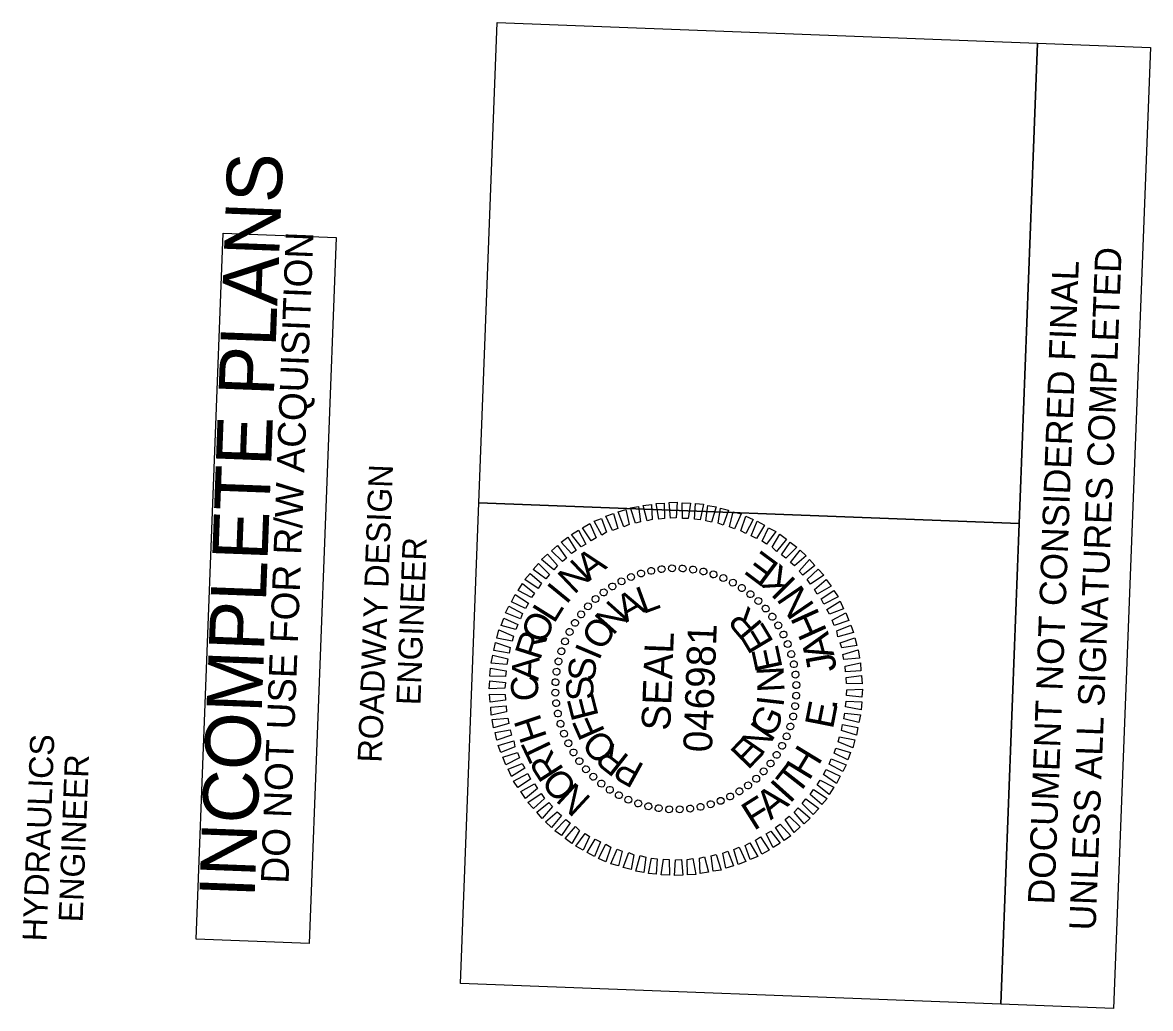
# Model space of a CAD drawing. Extents: x 2097431 to 2097897, y 685861 to 686794.
# Drawn here: x 2097476.5 to 2097570.4, y 686712.1 to 686794.1 of the extents above; entities that cross this region are included whole.
import ezdxf

# ---------------------------------------------------------------- set-up
doc = ezdxf.new("R2010")
doc.units = 0
for name, color, linetype in [('Sheet PE Seal Cell', 7, 'Continuous'), ('Sheet Profile CELL', 7, 'Continuous'), ('Sheet Sticker Exception Certification CELL', 7, 'Continuous'), ('Sheet Sticker Incomplete CELL', 7, 'Continuous')]:
    doc.layers.add(name, color=color, linetype=linetype)

msp = doc.modelspace()

# ---------------------------------------------------------------- linework, layer by layer
at = {"layer": 'Sheet PE Seal Cell'}
for p, q in [((2097527.187, 686748.023), (2097527.187, 686748.023)), ((2097527.998, 686748.312), (2097527.998, 686748.312)), ((2097528.847, 686748.52), (2097528.847, 686748.52)), ((2097529.732, 686748.646), (2097529.732, 686748.646)), ((2097530.596, 686748.733), (2097530.596, 686748.733)), ((2097531.476, 686748.719), (2097531.476, 686748.719)), ((2097532.353, 686748.625), (2097532.353, 686748.625)), ((2097533.207, 686748.453), (2097533.207, 686748.453)), ((2097534.04, 686748.241), (2097534.04, 686748.241)), ((2097534.869, 686747.929), (2097534.869, 686747.929)), ((2097525.615, 686747.223), (2097525.615, 686747.223)), ((2097526.392, 686747.653), (2097526.392, 686747.653)), ((2097535.654, 686747.538), (2097535.654, 686747.538)), ((2097536.418, 686747.109), (2097536.418, 686747.109)), ((2097524.214, 686746.176), (2097524.214, 686746.176)), ((2097524.896, 686746.75), (2097524.896, 686746.75)), ((2097537.119, 686746.581), (2097537.119, 686746.581)), ((2097537.797, 686746.015), (2097537.797, 686746.015)), ((2097523.59, 686745.579), (2097523.59, 686745.579)), ((2097538.394, 686745.392), (2097538.394, 686745.392)), ((2097522.497, 686744.2), (2097522.497, 686744.2)), ((2097523.024, 686744.9), (2097523.024, 686744.9)), ((2097538.968, 686744.709), (2097538.968, 686744.709)), ((2097522.067, 686743.436), (2097522.067, 686743.436)), ((2097539.441, 686743.99), (2097539.441, 686743.99)), ((2097539.872, 686743.213), (2097539.872, 686743.213)), ((2097521.677, 686742.65), (2097521.677, 686742.65)), ((2097540.241, 686742.419), (2097540.241, 686742.419)), ((2097521.365, 686741.822), (2097521.365, 686741.822)), ((2097540.53, 686741.607), (2097540.53, 686741.607)), ((2097521.153, 686740.989), (2097521.153, 686740.989)), ((2097540.738, 686740.758), (2097540.738, 686740.758)), ((2097520.98, 686740.135), (2097520.98, 686740.135)), ((2097540.864, 686739.873), (2097540.864, 686739.873)), ((2097520.886, 686739.258), (2097520.886, 686739.258)), ((2097530.912, 686738.693), (2097530.912, 686738.693)), ((2097540.951, 686739.009), (2097540.951, 686739.009)), ((2097520.872, 686738.378), (2097520.872, 686738.378)), ((2097540.937, 686738.129), (2097540.937, 686738.129)), ((2097520.959, 686737.514), (2097520.959, 686737.514)), ((2097521.085, 686736.628), (2097521.085, 686736.628)), ((2097540.844, 686737.252), (2097540.844, 686737.252)), ((2097521.293, 686735.78), (2097521.293, 686735.78)), ((2097540.671, 686736.398), (2097540.671, 686736.398)), ((2097521.582, 686734.968), (2097521.582, 686734.968)), ((2097540.459, 686735.565), (2097540.459, 686735.565)), ((2097521.952, 686734.173), (2097521.952, 686734.173)), ((2097539.756, 686733.951), (2097539.756, 686733.951)), ((2097540.147, 686734.737), (2097540.147, 686734.737)), ((2097522.382, 686733.396), (2097522.382, 686733.396)), ((2097539.327, 686733.187), (2097539.327, 686733.187)), ((2097522.855, 686732.678), (2097522.855, 686732.678)), ((2097523.43, 686731.995), (2097523.43, 686731.995)), ((2097538.8, 686732.487), (2097538.8, 686732.487)), ((2097524.026, 686731.372), (2097524.026, 686731.372)), ((2097537.61, 686731.211), (2097537.61, 686731.211)), ((2097538.233, 686731.808), (2097538.233, 686731.808)), ((2097524.705, 686730.805), (2097524.705, 686730.805)), ((2097525.405, 686730.278), (2097525.405, 686730.278)), ((2097536.209, 686730.164), (2097536.209, 686730.164)), ((2097536.927, 686730.637), (2097536.927, 686730.637)), ((2097526.169, 686729.849), (2097526.169, 686729.849)), ((2097526.955, 686729.458), (2097526.955, 686729.458)), ((2097527.784, 686729.146), (2097527.784, 686729.146)), ((2097534.637, 686729.364), (2097534.637, 686729.364)), ((2097535.432, 686729.734), (2097535.432, 686729.734)), ((2097528.616, 686728.934), (2097528.616, 686728.934)), ((2097529.47, 686728.761), (2097529.47, 686728.761)), ((2097530.347, 686728.668), (2097530.347, 686728.668)), ((2097531.227, 686728.654), (2097531.227, 686728.654)), ((2097532.091, 686728.741), (2097532.091, 686728.741)), ((2097532.977, 686728.867), (2097532.977, 686728.867)), ((2097533.825, 686729.075), (2097533.825, 686729.075))]:
    msp.add_line(p, q, dxfattribs=at)
for points in [[(2097526.586, 686752.189), (2097526.113, 686753.428), (2097526.741, 686753.624), (2097527.013, 686752.373)], [(2097527.557, 686752.472), (2097527.147, 686753.769), (2097527.811, 686753.863), (2097527.982, 686752.596)], [(2097528.526, 686752.675), (2097528.194, 686753.949), (2097528.878, 686754.043), (2097528.95, 686752.779)], [(2097529.492, 686752.818), (2097529.262, 686754.128), (2097529.944, 686754.162), (2097529.975, 686752.88)], [(2097530.456, 686752.901), (2097530.346, 686754.206), (2097531.027, 686754.22), (2097530.937, 686752.923)], [(2097531.456, 686752.883), (2097531.446, 686754.184), (2097532.125, 686754.158), (2097531.936, 686752.865)], [(2097532.454, 686752.825), (2097532.544, 686754.122), (2097533.202, 686754.057), (2097532.933, 686752.766)], [(2097533.41, 686752.688), (2097533.579, 686753.962), (2097534.255, 686753.856), (2097533.886, 686752.57)], [(2097534.423, 686752.489), (2097534.63, 686753.722), (2097535.305, 686753.556), (2097534.837, 686752.313)], [(2097524.758, 686751.499), (2097524.101, 686752.645), (2097524.731, 686752.881), (2097525.147, 686751.724)], [(2097525.633, 686751.865), (2097525.078, 686753.068), (2097525.728, 686753.303), (2097526.08, 686752.048)], [(2097535.372, 686752.192), (2097535.68, 686753.421), (2097536.334, 686753.256), (2097535.786, 686752.016)], [(2097536.32, 686751.856), (2097536.727, 686753.081), (2097537.337, 686752.798), (2097536.731, 686751.62)], [(2097537.184, 686751.422), (2097537.691, 686752.644), (2097538.299, 686752.32), (2097537.616, 686751.206)], [(2097523.019, 686750.525), (2097522.217, 686751.536), (2097522.812, 686751.894), (2097523.408, 686750.75)], [(2097523.859, 686751.013), (2097523.14, 686752.101), (2097523.754, 686752.458), (2097524.269, 686751.277)], [(2097538.088, 686750.987), (2097538.631, 686752.107), (2097539.239, 686751.784), (2097538.459, 686750.733)], [(2097522.217, 686749.955), (2097521.353, 686750.909), (2097521.909, 686751.308), (2097522.627, 686750.219)], [(2097538.929, 686750.475), (2097539.572, 686751.571), (2097540.116, 686751.15), (2097539.277, 686750.141)], [(2097539.706, 686749.845), (2097540.426, 686750.898), (2097540.991, 686750.496), (2097540.075, 686749.57)], [(2097520.744, 686748.59), (2097519.736, 686749.45), (2097520.234, 686749.911), (2097521.058, 686748.959)], [(2097521.471, 686749.283), (2097520.564, 686750.178), (2097521.062, 686750.64), (2097521.802, 686749.571)], [(2097540.442, 686749.216), (2097541.261, 686750.225), (2097541.764, 686749.766), (2097540.791, 686748.922)], [(2097520.095, 686747.855), (2097519.024, 686748.636), (2097519.484, 686749.139), (2097520.389, 686748.224)], [(2097541.175, 686748.487), (2097542.033, 686749.475), (2097542.474, 686748.958), (2097541.482, 686748.155)], [(2097519.464, 686747.058), (2097518.332, 686747.802), (2097518.771, 686748.306), (2097519.721, 686747.489)], [(2097541.849, 686747.801), (2097542.762, 686748.647), (2097543.223, 686748.149), (2097542.114, 686747.41)], [(2097518.894, 686746.3), (2097517.776, 686746.883), (2097518.139, 686747.469), (2097519.149, 686746.67)], [(2097542.438, 686746.978), (2097543.43, 686747.8), (2097543.829, 686747.245), (2097542.683, 686746.588)], [(2097518.399, 686745.398), (2097517.239, 686745.943), (2097517.543, 686746.551), (2097518.636, 686745.829)], [(2097543.008, 686746.195), (2097544.056, 686746.896), (2097544.415, 686746.362), (2097543.231, 686745.746)], [(2097517.985, 686744.513), (2097516.744, 686745.021), (2097517.005, 686745.571), (2097518.143, 686744.967)], [(2097543.474, 686745.297), (2097544.582, 686745.995), (2097544.878, 686745.363), (2097543.699, 686744.908)], [(2097517.591, 686743.628), (2097516.363, 686743.975), (2097516.587, 686744.587), (2097517.747, 686744.042)], [(2097543.921, 686744.419), (2097545.064, 686745.016), (2097545.32, 686744.385), (2097544.084, 686743.972)], [(2097517.294, 686742.678), (2097516.003, 686742.928), (2097516.189, 686743.601), (2097517.41, 686743.094)], [(2097544.307, 686743.524), (2097545.486, 686743.999), (2097545.703, 686743.39), (2097544.407, 686743.019)], [(2097517.035, 686741.667), (2097515.763, 686741.896), (2097515.889, 686742.552), (2097517.114, 686742.145)], [(2097544.589, 686742.532), (2097545.806, 686742.946), (2097545.962, 686742.319), (2097544.713, 686742.107)], [(2097516.839, 686740.714), (2097515.543, 686740.844), (2097515.688, 686741.499), (2097516.937, 686741.191)], [(2097544.812, 686741.563), (2097546.087, 686741.934), (2097546.201, 686741.249), (2097544.896, 686741.139)], [(2097516.741, 686739.717), (2097515.441, 686739.767), (2097515.487, 686740.426), (2097516.779, 686740.196)], [(2097544.995, 686740.595), (2097546.286, 686740.866), (2097546.321, 686740.204), (2097545.036, 686740.113)], [(2097545.078, 686739.631), (2097546.366, 686739.802), (2097546.419, 686739.119), (2097545.12, 686739.149)], [(2097516.684, 686738.759), (2097515.381, 686738.709), (2097515.426, 686739.367), (2097516.722, 686739.238)], [(2097545.14, 686738.628), (2097546.443, 686738.678), (2097546.397, 686738.019), (2097545.101, 686738.149)], [(2097516.745, 686737.756), (2097515.458, 686737.585), (2097515.404, 686738.267), (2097516.704, 686738.238)], [(2097545.083, 686737.67), (2097546.382, 686737.62), (2097546.337, 686736.961), (2097545.044, 686737.191)], [(2097516.828, 686736.792), (2097515.537, 686736.521), (2097515.502, 686737.183), (2097516.787, 686737.274)], [(2097544.985, 686736.673), (2097546.281, 686736.543), (2097546.135, 686735.888), (2097544.886, 686736.196)], [(2097517.012, 686735.824), (2097515.736, 686735.453), (2097515.623, 686736.137), (2097516.928, 686736.248)], [(2097544.788, 686735.719), (2097546.06, 686735.491), (2097545.935, 686734.835), (2097544.71, 686735.242)], [(2097517.235, 686734.855), (2097516.018, 686734.441), (2097515.862, 686735.067), (2097517.111, 686735.28)], [(2097517.517, 686733.863), (2097516.338, 686733.388), (2097516.121, 686733.997), (2097517.416, 686734.367)], [(2097544.529, 686734.709), (2097545.82, 686734.459), (2097545.634, 686733.786), (2097544.413, 686734.293)], [(2097517.903, 686732.968), (2097516.759, 686732.371), (2097516.503, 686733.001), (2097517.74, 686733.414)], [(2097543.838, 686732.874), (2097545.08, 686732.366), (2097544.818, 686731.815), (2097543.681, 686732.419)], [(2097544.232, 686733.759), (2097545.46, 686733.412), (2097545.236, 686732.8), (2097544.076, 686733.345)], [(2097518.349, 686732.09), (2097517.242, 686731.392), (2097516.946, 686732.024), (2097518.124, 686732.479)], [(2097543.424, 686731.989), (2097544.584, 686731.444), (2097544.28, 686730.835), (2097543.187, 686731.558)], [(2097518.815, 686731.191), (2097517.768, 686730.491), (2097517.408, 686731.025), (2097518.592, 686731.64)], [(2097542.929, 686731.087), (2097544.048, 686730.504), (2097543.685, 686729.917), (2097542.675, 686730.717)], [(2097519.386, 686730.409), (2097518.393, 686729.586), (2097517.994, 686730.142), (2097519.141, 686730.799)], [(2097542.36, 686730.329), (2097543.492, 686729.585), (2097543.052, 686729.081), (2097542.103, 686729.898)], [(2097519.975, 686729.586), (2097519.062, 686728.74), (2097518.6, 686729.238), (2097519.709, 686729.976)], [(2097520.649, 686728.9), (2097519.79, 686727.912), (2097519.35, 686728.429), (2097520.341, 686729.232)], [(2097541.729, 686729.532), (2097542.799, 686728.751), (2097542.34, 686728.248), (2097541.434, 686729.163)], [(2097521.381, 686728.171), (2097520.562, 686727.162), (2097520.059, 686727.621), (2097521.032, 686728.464)], [(2097541.08, 686728.796), (2097542.088, 686727.937), (2097541.59, 686727.476), (2097540.766, 686728.428)], [(2097522.118, 686727.542), (2097521.397, 686726.489), (2097520.832, 686726.891), (2097521.748, 686727.817)], [(2097522.894, 686726.912), (2097522.252, 686725.816), (2097521.708, 686726.237), (2097522.547, 686727.246)], [(2097539.607, 686727.432), (2097540.471, 686726.478), (2097539.915, 686726.079), (2097539.196, 686727.167)], [(2097540.353, 686728.104), (2097541.259, 686727.208), (2097540.761, 686726.747), (2097540.022, 686727.816)], [(2097523.735, 686726.399), (2097523.192, 686725.279), (2097522.584, 686725.603), (2097523.365, 686726.654)], [(2097537.965, 686726.374), (2097538.684, 686725.286), (2097538.069, 686724.929), (2097537.554, 686726.11)], [(2097538.804, 686726.862), (2097539.606, 686725.851), (2097539.012, 686725.493), (2097538.415, 686726.637)], [(2097524.639, 686725.964), (2097524.132, 686724.743), (2097523.524, 686725.067), (2097524.207, 686726.181)], [(2097525.503, 686725.531), (2097525.096, 686724.306), (2097524.486, 686724.589), (2097525.092, 686725.767)], [(2097526.451, 686725.194), (2097526.144, 686723.965), (2097525.49, 686724.13), (2097526.038, 686725.37)], [(2097536.191, 686725.521), (2097536.745, 686724.319), (2097536.096, 686724.084), (2097535.743, 686725.338)], [(2097537.065, 686725.888), (2097537.722, 686724.742), (2097537.093, 686724.506), (2097536.677, 686725.663)], [(2097527.4, 686724.898), (2097527.193, 686723.665), (2097526.519, 686723.831), (2097526.987, 686725.074)], [(2097528.414, 686724.699), (2097528.245, 686723.424), (2097527.568, 686723.53), (2097527.938, 686724.817)], [(2097529.369, 686724.562), (2097529.279, 686723.265), (2097528.621, 686723.33), (2097528.891, 686724.621)], [(2097530.368, 686724.504), (2097530.378, 686723.202), (2097529.698, 686723.229), (2097529.888, 686724.522)], [(2097531.368, 686724.485), (2097531.478, 686723.18), (2097530.797, 686723.166), (2097530.886, 686724.464)], [(2097532.331, 686724.569), (2097532.561, 686723.259), (2097531.88, 686723.225), (2097531.849, 686724.507)], [(2097533.298, 686724.712), (2097533.629, 686723.438), (2097532.945, 686723.344), (2097532.873, 686724.608)], [(2097534.266, 686724.915), (2097534.677, 686723.618), (2097534.013, 686723.523), (2097533.841, 686724.791)], [(2097535.238, 686725.198), (2097535.711, 686723.959), (2097535.083, 686723.763), (2097534.81, 686725.014)]]:
    msp.add_lwpolyline(points, close=True, dxfattribs=at)
for centre, major_axis in [((2097528.86, 686748.513), (-0.059, 0.282)), ((2097529.723, 686748.655), (-0.034, 0.286)), ((2097530.596, 686748.72), (-0.009, 0.288)), ((2097531.471, 686748.71), (0.016, 0.288)), ((2097532.342, 686748.623), (0.041, 0.285)), ((2097526.388, 686747.648), (-0.13, 0.257)), ((2097527.186, 686748.008), (-0.107, 0.267)), ((2097528.012, 686748.297), (-0.083, 0.276)), ((2097533.202, 686748.46), (0.066, 0.28)), ((2097534.044, 686748.224), (0.09, 0.274)), ((2097534.863, 686747.914), (0.113, 0.265)), ((2097524.902, 686746.726), (-0.173, 0.231)), ((2097525.625, 686747.219), (-0.152, 0.245)), ((2097535.652, 686747.535), (0.136, 0.254)), ((2097536.404, 686747.088), (0.158, 0.241)), ((2097524.225, 686746.172), (-0.192, 0.215)), ((2097537.115, 686746.578), (0.178, 0.226)), ((2097537.779, 686746.007), (0.197, 0.21)), ((2097523.028, 686744.897), (-0.226, 0.178)), ((2097523.598, 686745.56), (-0.21, 0.197)), ((2097538.39, 686745.381), (0.215, 0.192)), ((2097522.517, 686744.186), (-0.241, 0.158)), ((2097538.944, 686744.703), (0.231, 0.173)), ((2097539.437, 686743.98), (0.245, 0.152)), ((2097522.07, 686743.433), (-0.254, 0.136)), ((2097539.866, 686743.217), (0.257, 0.13)), ((2097521.691, 686742.645), (-0.265, 0.113)), ((2097540.226, 686742.42), (0.267, 0.107)), ((2097521.381, 686741.826), (-0.274, 0.09)), ((2097540.515, 686741.594), (0.276, 0.083)), ((2097520.982, 686740.124), (-0.285, 0.041)), ((2097521.145, 686740.984), (-0.28, 0.066)), ((2097540.732, 686740.746), (0.282, 0.059)), ((2097520.895, 686739.253), (-0.288, 0.016)), ((2097540.873, 686739.882), (0.286, 0.034)), ((2097520.885, 686738.378), (-0.288, -0.009)), ((2097540.939, 686739.009), (0.288, 0.009)), ((2097520.95, 686737.505), (-0.286, -0.034)), ((2097540.841, 686737.263), (0.285, -0.041)), ((2097540.928, 686738.134), (0.288, -0.016)), ((2097521.092, 686736.641), (-0.282, -0.059)), ((2097540.679, 686736.403), (0.28, -0.066)), ((2097521.308, 686735.793), (-0.276, -0.083)), ((2097540.442, 686735.561), (0.274, -0.09)), ((2097521.597, 686734.967), (-0.267, -0.107)), ((2097540.133, 686734.742), (0.265, -0.113)), ((2097521.958, 686734.17), (-0.257, -0.13)), ((2097539.753, 686733.953), (0.254, -0.136)), ((2097522.386, 686733.406), (-0.245, -0.152)), ((2097522.879, 686732.683), (-0.231, -0.173)), ((2097539.306, 686733.201), (0.241, -0.158)), ((2097523.434, 686732.006), (-0.215, -0.192)), ((2097538.225, 686731.826), (0.21, -0.197)), ((2097538.796, 686732.49), (0.226, -0.178)), ((2097524.045, 686731.38), (-0.197, -0.21)), ((2097524.708, 686730.809), (-0.178, -0.226)), ((2097537.599, 686731.215), (0.192, -0.215)), ((2097525.419, 686730.299), (-0.158, -0.241)), ((2097526.172, 686729.852), (-0.136, -0.254)), ((2097535.435, 686729.739), (0.13, -0.257)), ((2097536.199, 686730.168), (0.152, -0.245)), ((2097536.922, 686730.661), (0.173, -0.231)), ((2097526.96, 686729.472), (-0.113, -0.265)), ((2097527.779, 686729.163), (-0.09, -0.274)), ((2097528.622, 686728.926), (-0.066, -0.28)), ((2097532.964, 686728.874), (0.059, -0.282)), ((2097533.812, 686729.09), (0.083, -0.276)), ((2097534.638, 686729.379), (0.107, -0.267)), ((2097529.481, 686728.764), (-0.041, -0.285)), ((2097530.352, 686728.677), (-0.016, -0.288)), ((2097531.227, 686728.666), (0.009, -0.288)), ((2097532.1, 686728.732), (0.034, -0.286))]:
    msp.add_ellipse(centre, major_axis=major_axis, ratio=0.999708, dxfattribs=at)
at = {"layer": 'Sheet Profile CELL'}
for points in [[(2097514.516, 686754.173), (2097516.049, 686794.144), (2097561.016, 686792.419), (2097559.483, 686752.449)], [(2097512.982, 686714.183), (2097514.516, 686754.173), (2097559.483, 686752.449), (2097557.949, 686712.458)]]:
    msp.add_lwpolyline(points, close=True, dxfattribs=at)
at = {"layer": 'Sheet Sticker Exception Certification CELL'}
for p, q in [((2097557.949, 686712.463), (2097561.016, 686792.419)), ((2097561.021, 686792.419), (2097570.414, 686792.059)), ((2097570.409, 686792.059), (2097567.342, 686712.103)), ((2097567.342, 686712.103), (2097557.949, 686712.463))]:
    msp.add_line(p, q, dxfattribs=at)
at = {"layer": 'Sheet Sticker Incomplete CELL'}
msp.add_lwpolyline([(2097500.382, 686717.508), (2097490.989, 686717.869), (2097493.242, 686776.626), (2097502.635, 686776.265)], close=True, dxfattribs=at)

# ---------------------------------------------------------------- texts
at = {"layer": 'Sheet PE Seal Cell'}
for s, height, rotation, p in [('A', 2.256, 36.42085, (2097523.668, 686747.618)), ('E', 2.399, 143.29672, (2097539.63, 686749.008)), ('N', 2.256, 43.62261, (2097522.444, 686746.484)), ('K', 2.399, 135.0128, (2097541.025, 686747.644)), ('I', 2.255, 50.82384, (2097521.792, 686745.648)), ('L', 2.256, 20.20455, (2097528.168, 686744.903)), ('N', 2.399, 124.28697, (2097542.514, 686745.605)), ('N', 2.255, 48.28031, (2097525.676, 686743.077)), ('A', 2.256, 29.56397, (2097526.759, 686744.177)), ('L', 2.255, 58.02457, (2097520.77, 686744.066)), ('R', 2.256, 130.28511, (2097538.223, 686744.057)), ('H', 2.399, 114.30299, (2097543.537, 686743.489)), ('O', 2.255, 65.22486, (2097519.963, 686742.336)), ('O', 2.255, 57.63718, (2097524.825, 686741.769)), ('E', 2.255, 120.92779, (2097539.108, 686742.602)), ('R', 2.255, 72.4248, (2097519.612, 686741.008)), ('SEAL', 2.3993, 87.8037, (2097530.438, 686735.189)), ('046981', 2.3993, 87.8037, (2097533.914, 686733.386)), ('A', 2.399, 105.46268, (2097544.124, 686741.492)), ('I', 2.255, 66.9933, (2097524.515, 686740.98)), ('E', 2.255, 102.21546, (2097539.806, 686740.454)), ('A', 2.255, 86.82402, (2097519.468, 686739.332)), ('J', 2.399, 100.20486, (2097544.325, 686740.269)), ('S', 2.255, 85.7041, (2097524.169, 686739.272)), ('N', 2.255, 92.86009, (2097539.97, 686738.466)), ('C', 2.255, 94.02357, (2097519.527, 686737.749)), ('S', 2.255, 95.05931, (2097524.134, 686737.833)), ('E', 2.255, 104.41477, (2097524.501, 686736.437)), ('I', 2.255, 83.5049, (2097539.858, 686737.129)), ('E', 2.399, 78.86139, (2097543.979, 686735.279)), ('G', 2.255, 64.79394, (2097538.998, 686734.54)), ('.', 2.399, 85.97073, (2097544.301, 686736.923)), ('H', 2.255, 108.42318, (2097520.21, 686734.681)), ('F', 2.255, 113.77073, (2097525.051, 686735.135)), ('N', 2.255, 55.43766, (2097538.041, 686733.056)), ('O', 2.256, 132.48494, (2097526.18, 686733.771)), ('E', 2.255, 46.08059, (2097536.916, 686731.898)), ('T', 2.255, 115.62347, (2097520.82, 686733.356)), ('R', 2.256, 141.84335, (2097527.132, 686733.034)), ('H', 2.399, 58.67705, (2097541.998, 686730.98)), ('R', 2.255, 122.82421, (2097521.647, 686731.964)), ('P', 2.256, 151.20259, (2097528.387, 686732.346)), ('T', 2.399, 51.87681, (2097541.007, 686729.722)), ('O', 2.255, 130.02544, (2097522.833, 686730.537)), ('I', 2.399, 48.07486, (2097540.39, 686729.072)), ('N', 2.256, 137.2272, (2097523.957, 686729.573)), ('A', 2.399, 39.23455, (2097538.799, 686727.73)), ('F', 2.399, 32.21794, (2097537.4, 686726.849))]:
    msp.add_text(s, height=height, rotation=rotation, dxfattribs=at).set_placement(p)
at = {"layer": 'Sheet Profile CELL'}
for s, height, p in [('ROADWAY DESIGN', 2.00004, (2097506.418, 686732.534)), ('ENGINEER', 2, (2097509.644, 686737.314)), ('HYDRAULICS', 2, (2097478.523, 686717.659)), ('ENGINEER', 2, (2097481.526, 686719.245))]:
    msp.add_text(s, height=height, rotation=87.8037, dxfattribs=at).set_placement(p)
at = {"layer": 'Sheet Sticker Exception Certification CELL'}
for s, p in [('UNLESS ALL SIGNATURES COMPLETED', (2097565.847, 686718.565)), ('DOCUMENT NOT CONSIDERED FINAL', (2097562.407, 686720.727))]:
    msp.add_text(s, height=2.2, rotation=87.8037, dxfattribs=at).set_placement(p)
at = {"layer": 'Sheet Sticker Incomplete CELL'}
for s, height, p in [('INCOMPLETE PLANS', 4.608, (2097495.843, 686721.265)), ('DO NOT USE FOR R/W ACQUISITION', 2.304, (2097498.67, 686722.458))]:
    msp.add_text(s, height=height, rotation=87.8037, dxfattribs=at).set_placement(p)

doc.saveas('drawing.dxf')
